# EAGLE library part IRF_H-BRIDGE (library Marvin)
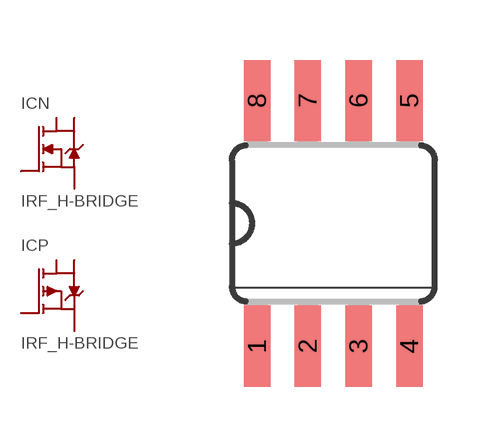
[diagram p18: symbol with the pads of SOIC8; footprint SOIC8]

Designator prefix IC; gates N=NMOS2D P=PMOS2D

## IRF_H-BRIDGEN  [SOIC8]
1  N:S  pas
2  N:G  pas
3  P:S  pas
4  P:G  pas
5  P:D2  pas
6  P:D1  pas
7  N:D2  pas
8  N:D1  pas

## Footprint SOIC8 (pad centres in mm)
smd 0.66 x 2.032: 1 -1.905,-3.073; 2 -0.635,-3.073; 3 0.635,-3.073; 4 1.905,-3.073; 5 1.905,3.073; 6 0.635,3.073; 7 -0.635,3.073; 8 -1.905,3.073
